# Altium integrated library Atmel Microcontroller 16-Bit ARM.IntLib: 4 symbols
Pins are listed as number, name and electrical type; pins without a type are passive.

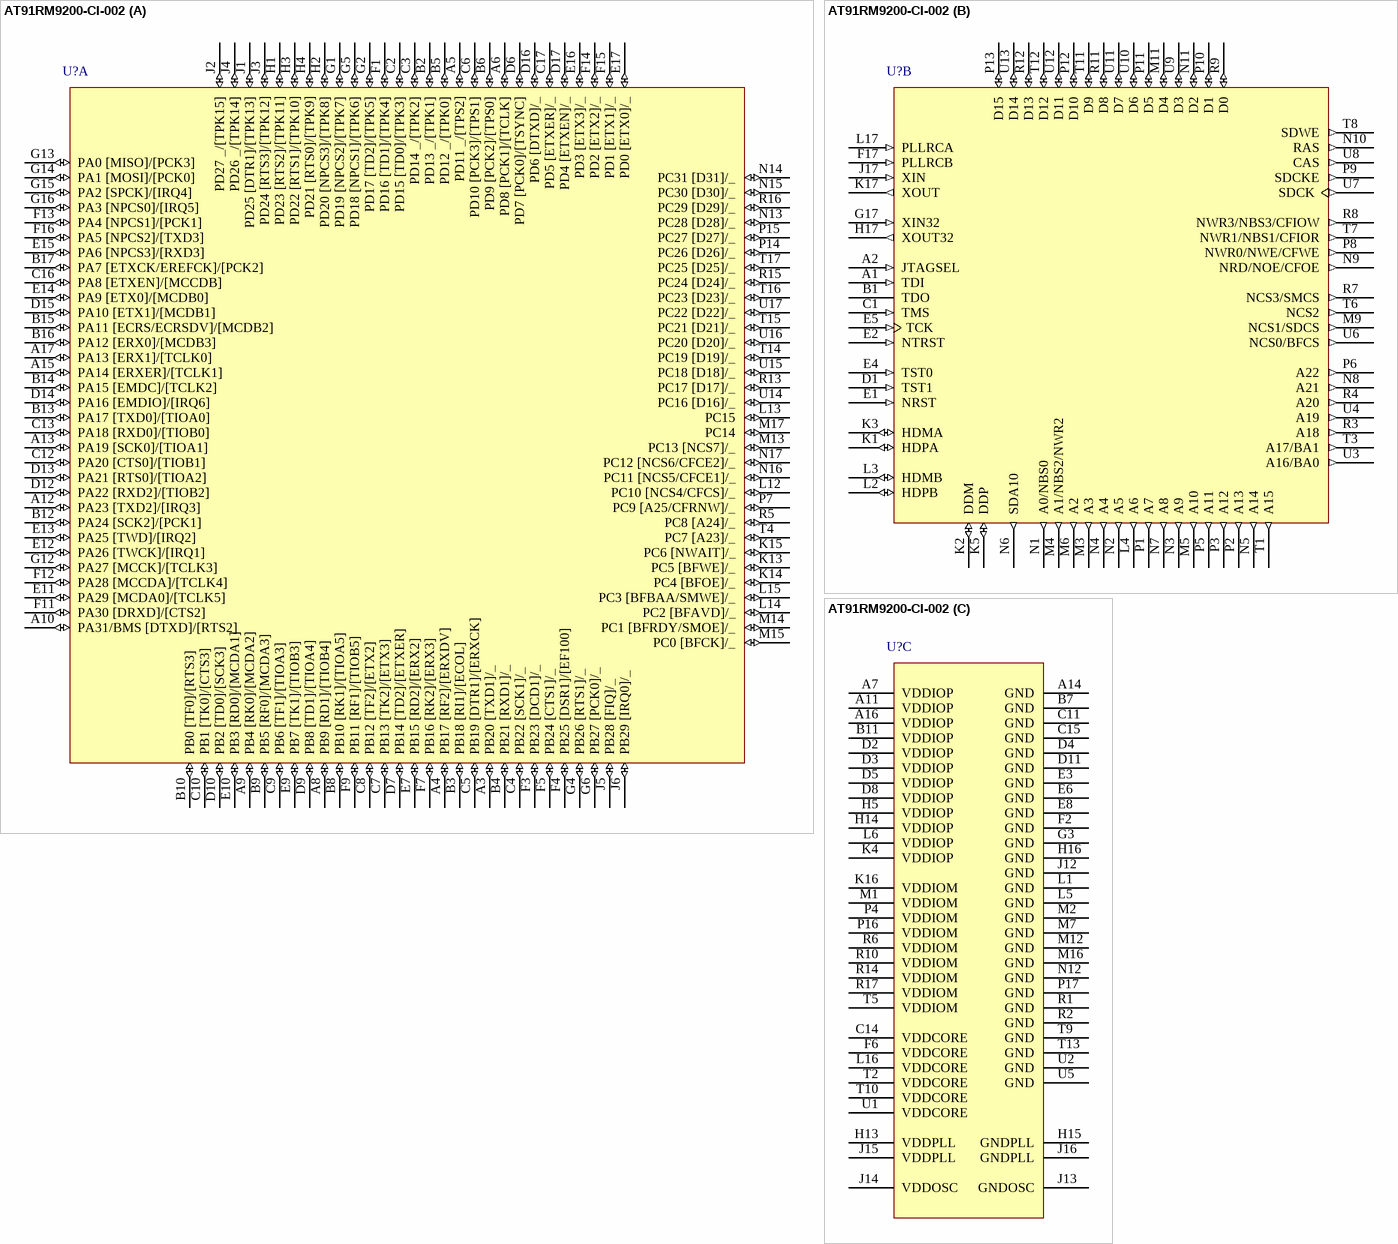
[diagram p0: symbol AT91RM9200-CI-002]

## AT91RM9200-CI-002
designator U?
16-Bit ARM Microcontroller, ARM9TDMI 32-bit RISC CPU, 16KB Instruction and 16KB Data caches, 256-Ball BGA, Industrial; Note: The Pin names in [ ] brackets indicate peripheral multiplexing function.
footprint BGA256 (BGA, 256-Leads, Body 15x15mm, Pitch 0.8mm)
3D model AT91RM9200-BGA256 (256-Ball Ball Grid Array 0.8 mm Pitch)
part A pins: A3 PB20 [TXD1]/_ (io), A4 PB17 [RF2]/[ERXDV] (io), A5 PD11 _/[TPS2] (io), A6 PD8 [PCK1]/[TCLK] (io), A8 PB9 [RD1]/[TIOB4] (io), A9 PB4 [RK0]/[MCDA2] (io), A10 PA31/BMS [DTXD]/[RTS2] (io), A12 PA23 [TXD2]/[IRQ3] (io), A13 PA19 [SCK0]/[TIOA1] (io), A15 PA14 [ERXER]/[TCLK1] (io), A17 PA13 [ERX1]/[TCLK0] (io), B2 PD13 _/[TPK1] (io), B3 PB18 [RI1]/[ECOL] (io), B4 PB21 [RXD1]/_ (io), B5 PD12 _/[TPK0] (io), B6 PD9 [PCK2]/[TPS0] (io), B8 PB10 [RK1]/[TIOA5] (io), B9 PB5 [RF0]/[MCDA3] (io), B10 PB0 [TF0]/[RTS3] (io), B12 PA24 [SCK2]/[PCK1] (io), B13 PA17 [TXD0]/[TIOA0] (io), B14 PA15 [EMDC]/[TCLK2] (io), B15 PA11 [ECRS/ECRSDV]/[MCDB2] (io), B16 PA12 [ERX0]/[MCDB3] (io), B17 PA7 [ETXCK/EREFCK]/[PCK2] (io), C2 PD15 [TD0]/[TPK3] (io), C3 PD14 _/[TPK2] (io), C4 PB22 [SCK1]/_ (io), C5 PB19 [DTR1]/[ERXCK] (io), C6 PD10 [PCK3]/[TPS1] (io), C7 PB13 [TK2]/[ETX3] (io), C8 PB12 [TF2]/[ETX2] (io), C9 PB6 [TF1]/[TIOA3] (io), C10 PB1 [TK0]/[CTS3] (io), C12 PA20 [CTS0]/[TIOB1] (io), C13 PA18 [RXD0]/[TIOB0] (io), C16 PA8 [ETXEN]/[MCCDB] (io), C17 PD5 [ETXER]/_ (io), D6 PD7 [PCK0]/[TSYNC] (io), D7 PB14 [TD2]/[ETXER] (io), D9 PB8 [TD1]/[TIOA4] (io), D10 PB2 [TD0]/[SCK3] (io), D12 PA22 [RXD2]/[TIOB2] (io), D13 PA21 [RTS0]/[TIOA2] (io), D14 PA16 [EMDIO]/[IRQ6] (io), D15 PA10 [ETX1]/[MCDB1] (io), D16 PD6 [DTXD]/_ (io), D17 PD4 [ETXEN]/_ (io), E7 PB15 [RD2]/[ERX2] (io), E9 PB7 [TK1]/[TIOB3] (io), E10 PB3 [RD0]/[MCDA1] (io), E11 PA29 [MCDA0]/[TCLK5] (io), E12 PA26 [TWCK]/[IRQ1] (io), E13 PA25 [TWD]/[IRQ2] (io), E14 PA9 [ETX0]/[MCDB0] (io), E15 PA6 [NPCS3]/[RXD3] (io), E16 PD3 [ETX3]/_ (io), E17 PD0 [ETX0]/_ (io), F1 PD16 [TD1]/[TPK4] (io), F3 PB23 [DCD1]/_ (io), F4 PB25 [DSR1]/[EF100] (io), F5 PB24 [CTS1]/_ (io), F7 PB16 [RK2]/[ERX3] (io), F9 PB11 [RF1]/[TIOB5] (io), F11 PA30 [DRXD]/[CTS2] (io), F12 PA28 [MCCDA]/[TCLK4] (io), F13 PA4 [NPCS1]/[PCK1] (io), F14 PD2 [ETX2]/_ (io), F15 PD1 [ETX1]/_ (io), F16 PA5 [NPCS2]/[TXD3] (io), G1 PD19 [NPCS2]/[TPK7] (io), G2 PD17 [TD2]/[TPK5] (io), G4 PB26 [RTS1]/_ (io), G5 PD18 [NPCS1]/[TPK6] (io), G6 PB27 [PCK0]/_ (io), G12 PA27 [MCCK]/[TCLK3] (io), G13 PA0 [MISO]/[PCK3] (io), G14 PA1 [MOSI]/[PCK0] (io), G15 PA2 [SPCK]/[IRQ4] (io), G16 PA3 [NPCS0]/[IRQ5] (io), H1 PD23 [RTS2]/[TPK11] (io), H2 PD20 [NPCS3]/[TPK8] (io), H3 PD22 [RTS1]/[TPK10] (io), H4 PD21 [RTS0]/[TPK9] (io), J1 PD25 [DTR1]/[TPK13] (io), J2 PD27 _/[TPK15] (io), J3 PD24 [RTS3]/[TPK12] (io), J4 PD26 _/[TPK14] (io), J5 PB28 [FIQ]/_ (io), J6 PB29 [IRQ0]/_ (io), K13 PC5 [BFWE]/_ (io), K14 PC4 [BFOE]/_ (io), K15 PC6 [NWAIT]/_ (io), L12 PC10 [NCS4/CFCS]/_ (io), L13 PC15 (io), L14 PC2 [BFAVD]/_ (io), L15 PC3 [BFBAA/SMWE]/_ (io), M13 PC13 [NCS7]/_ (io), M14 PC1 [BFRDY/SMOE]/_ (io), M15 PC0 [BFCK]/_ (io), M17 PC14 (io), N13 PC28 [D28]/_ (io), N14 PC31 [D31]/_ (io), N15 PC30 [D30]/_ (io), N16 PC11 [NCS5/CFCE1]/_ (io), N17 PC12 [NCS6/CFCE2]/_ (io), P7 PC9 [A25/CFRNW]/_ (io), P14 PC26 [D26]/_ (io), P15 PC27 [D27]/_ (io), R5 PC8 [A24]/_ (io), R13 PC17 [D17]/_ (io), R15 PC24 [D24]/_ (io), R16 PC29 [D29]/_ (io), T4 PC7 [A23]/_ (io), T14 PC19 [D19]/_ (io), T15 PC21 [D21]/_ (io), T16 PC23 [D23]/_ (io), T17 PC25 [D25]/_ (io), U14 PC16 [D16]/_ (io), U15 PC18 [D18]/_ (io), U16 PC20 [D20]/_ (io), U17 PC22 [D22]/_ (io)
part B pins: A1 TDI (in), A2 JTAGSEL (in), B1 TDO (hiz), C1 TMS (in), D1 TST1 (in), E1 NRST (in), E2 NTRST (in), E4 TST0 (in), E5 TCK (in), F17 PLLRCB (in), G17 XIN32 (in), H17 XOUT32 (out), J17 XIN (in), K1 HDPA (io), K2 DDM (io), K3 HDMA (io), K5 DDP (io), K17 XOUT (out), L2 HDPB (io), L3 HDMB (io), L4 A6 (out), L17 PLLRCA (in), M3 A3 (out), M4 A1/NBS2/NWR2 (out), M5 A10 (out), M6 A2 (out), M9 NCS1/SDCS (out), M11 D4 (io), N1 A0/NBS0 (out), N2 A5 (out), N3 A9 (out), N4 A4 (out), N5 A14 (out), N6 SDA10 (out), N7 A8 (out), N8 A21 (out), N9 NRD/NOE/CFOE (out), N10 RAS (out), N11 D2 (io), P1 A7 (out), P2 A13 (out), P3 A12 (out), P5 A11 (out), P6 A22 (out), P8 NWR0/NWE/CFWE (out), P9 SDCKE (out), P10 D1 (io), P11 D5 (io), P12 D10 (io), P13 D15 (io), R3 A18 (out), R4 A20 (out), R7 NCS3/SMCS (out), R8 NWR3/NBS3/CFIOW (out), R9 D0 (io), R11 D8 (io), R12 D13 (io), T1 A15 (out), T3 A17/BA1 (out), T6 NCS2 (out), T7 NWR1/NBS1/CFIOR (out), T8 SDWE (out), T11 D9 (io), T12 D12 (io), U3 A16/BA0 (out), U4 A19 (out), U6 NCS0/BFCS (out), U7 SDCK (out), U8 CAS (out), U9 D3 (io), U10 D6 (io), U11 D7 (io), U12 D11 (io), U13 D14 (io)
part C pins: A7 VDDIOP (power), A11 VDDIOP (power), A14 GND (power), A16 VDDIOP (power), B7 GND (power), B11 VDDIOP (power), C11 GND (power), C14 VDDCORE (power), C15 GND (power), D2 VDDIOP (power), D3 VDDIOP (power), D4 GND (power), D5 VDDIOP (power), D8 VDDIOP (power), D11 GND (power), E3 GND (power), E6 GND (power), E8 GND (power), F2 GND (power), F6 VDDCORE (power), G3 GND (power), H5 VDDIOP (power), H13 VDDPLL (power), H14 VDDIOP (power), H15 GNDPLL (power), H16 GND (power), J12 GND (power), J13 GNDOSC (power), J14 VDDOSC (power), J15 VDDPLL (power), J16 GNDPLL (power), K4 VDDIOP (power), K16 VDDIOM (power), L1 GND (power), L5 GND (power), L6 VDDIOP (power), L16 VDDCORE (power), M1 VDDIOM (power), M2 GND (power), M7 GND (power), M12 GND (power), M16 GND (power), N12 GND (power), P4 VDDIOM (power), P16 VDDIOM (power), P17 GND (power), R1 GND (power), R2 GND (power), R6 VDDIOM (power), R10 VDDIOM (power), R14 VDDIOM (power), R17 VDDIOM (power), T2 VDDCORE (power), T5 VDDIOM (power), T9 GND (power), T10 VDDCORE (power), T13 GND (power), U1 VDDCORE (power), U2 GND (power), U5 GND (power)

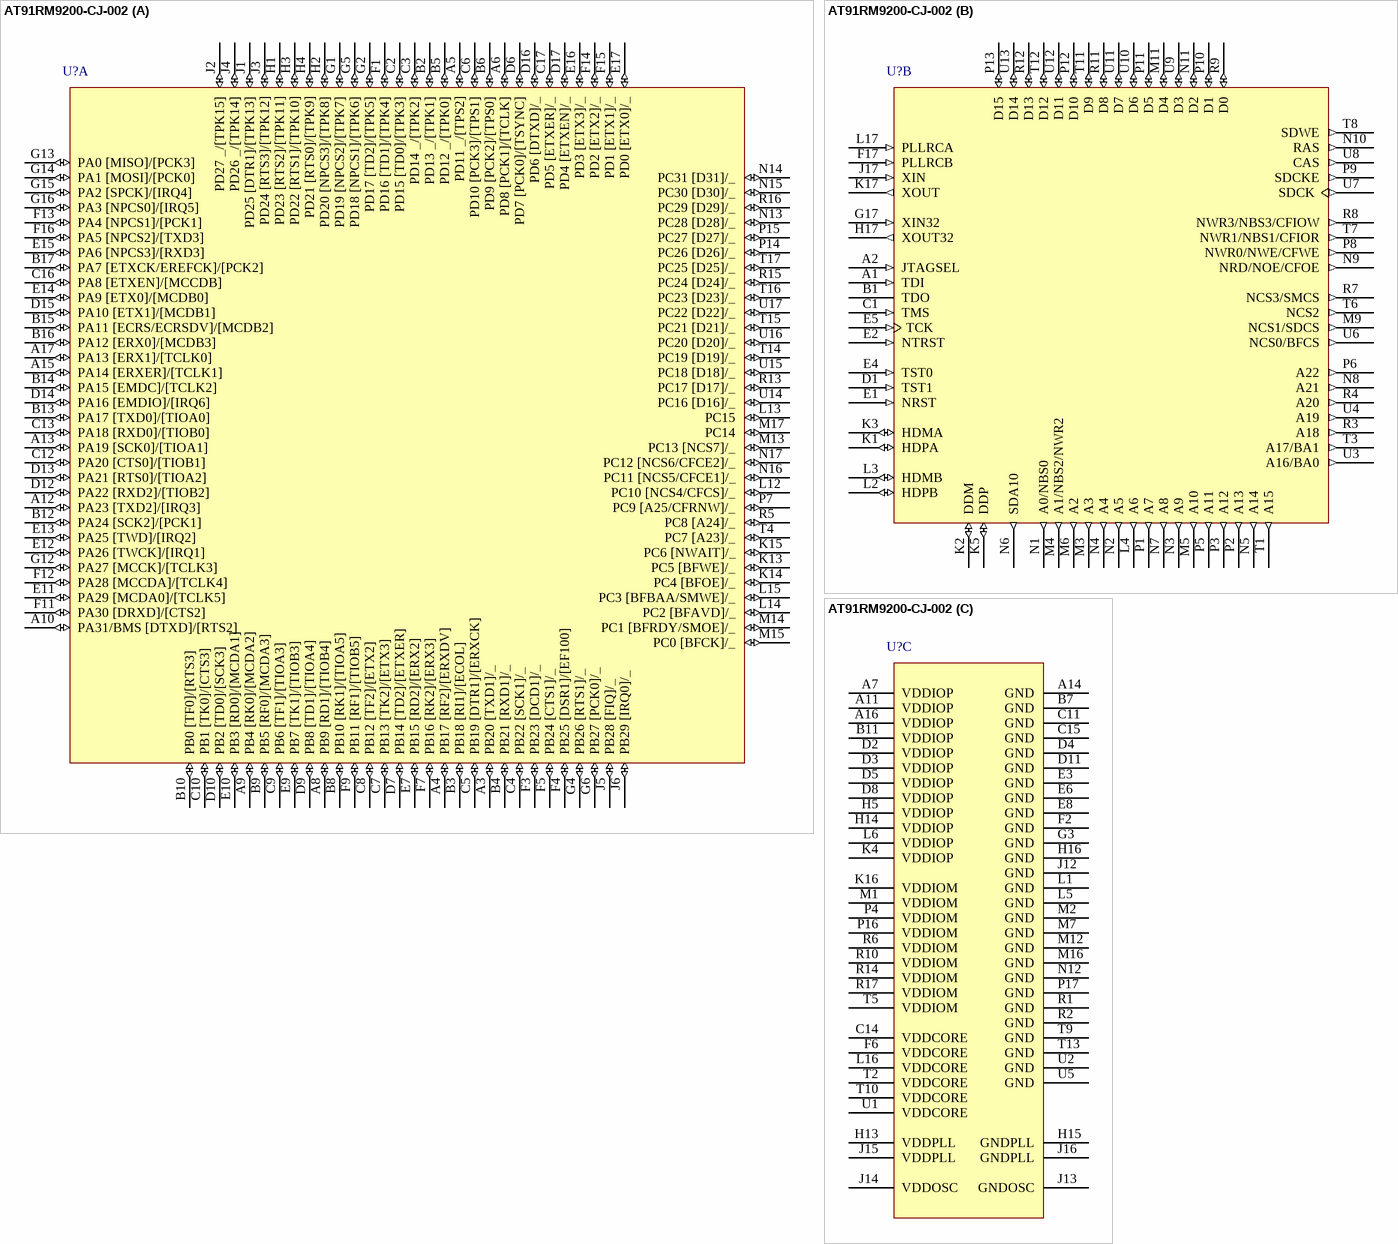
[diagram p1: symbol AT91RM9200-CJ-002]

## AT91RM9200-CJ-002
designator U?
16-Bit ARM Microcontroller, ARM9TDMI 32-bit RISC CPU, 16KB Instruction and 16KB Data caches, 256-Ball BGA, Industrial, Pb-free; Note: The Pin names in [ ] brackets indicate peripheral multiplexing function.
footprint BGA256 (BGA, 256-Leads, Body 15x15mm, Pitch 0.8mm)
3D model AT91RM9200-BGA256 (256-Ball Ball Grid Array 0.8 mm Pitch)
part A pins: A3 PB20 [TXD1]/_ (io), A4 PB17 [RF2]/[ERXDV] (io), A5 PD11 _/[TPS2] (io), A6 PD8 [PCK1]/[TCLK] (io), A8 PB9 [RD1]/[TIOB4] (io), A9 PB4 [RK0]/[MCDA2] (io), A10 PA31/BMS [DTXD]/[RTS2] (io), A12 PA23 [TXD2]/[IRQ3] (io), A13 PA19 [SCK0]/[TIOA1] (io), A15 PA14 [ERXER]/[TCLK1] (io), A17 PA13 [ERX1]/[TCLK0] (io), B2 PD13 _/[TPK1] (io), B3 PB18 [RI1]/[ECOL] (io), B4 PB21 [RXD1]/_ (io), B5 PD12 _/[TPK0] (io), B6 PD9 [PCK2]/[TPS0] (io), B8 PB10 [RK1]/[TIOA5] (io), B9 PB5 [RF0]/[MCDA3] (io), B10 PB0 [TF0]/[RTS3] (io), B12 PA24 [SCK2]/[PCK1] (io), B13 PA17 [TXD0]/[TIOA0] (io), B14 PA15 [EMDC]/[TCLK2] (io), B15 PA11 [ECRS/ECRSDV]/[MCDB2] (io), B16 PA12 [ERX0]/[MCDB3] (io), B17 PA7 [ETXCK/EREFCK]/[PCK2] (io), C2 PD15 [TD0]/[TPK3] (io), C3 PD14 _/[TPK2] (io), C4 PB22 [SCK1]/_ (io), C5 PB19 [DTR1]/[ERXCK] (io), C6 PD10 [PCK3]/[TPS1] (io), C7 PB13 [TK2]/[ETX3] (io), C8 PB12 [TF2]/[ETX2] (io), C9 PB6 [TF1]/[TIOA3] (io), C10 PB1 [TK0]/[CTS3] (io), C12 PA20 [CTS0]/[TIOB1] (io), C13 PA18 [RXD0]/[TIOB0] (io), C16 PA8 [ETXEN]/[MCCDB] (io), C17 PD5 [ETXER]/_ (io), D6 PD7 [PCK0]/[TSYNC] (io), D7 PB14 [TD2]/[ETXER] (io), D9 PB8 [TD1]/[TIOA4] (io), D10 PB2 [TD0]/[SCK3] (io), D12 PA22 [RXD2]/[TIOB2] (io), D13 PA21 [RTS0]/[TIOA2] (io), D14 PA16 [EMDIO]/[IRQ6] (io), D15 PA10 [ETX1]/[MCDB1] (io), D16 PD6 [DTXD]/_ (io), D17 PD4 [ETXEN]/_ (io), E7 PB15 [RD2]/[ERX2] (io), E9 PB7 [TK1]/[TIOB3] (io), E10 PB3 [RD0]/[MCDA1] (io), E11 PA29 [MCDA0]/[TCLK5] (io), E12 PA26 [TWCK]/[IRQ1] (io), E13 PA25 [TWD]/[IRQ2] (io), E14 PA9 [ETX0]/[MCDB0] (io), E15 PA6 [NPCS3]/[RXD3] (io), E16 PD3 [ETX3]/_ (io), E17 PD0 [ETX0]/_ (io), F1 PD16 [TD1]/[TPK4] (io), F3 PB23 [DCD1]/_ (io), F4 PB25 [DSR1]/[EF100] (io), F5 PB24 [CTS1]/_ (io), F7 PB16 [RK2]/[ERX3] (io), F9 PB11 [RF1]/[TIOB5] (io), F11 PA30 [DRXD]/[CTS2] (io), F12 PA28 [MCCDA]/[TCLK4] (io), F13 PA4 [NPCS1]/[PCK1] (io), F14 PD2 [ETX2]/_ (io), F15 PD1 [ETX1]/_ (io), F16 PA5 [NPCS2]/[TXD3] (io), G1 PD19 [NPCS2]/[TPK7] (io), G2 PD17 [TD2]/[TPK5] (io), G4 PB26 [RTS1]/_ (io), G5 PD18 [NPCS1]/[TPK6] (io), G6 PB27 [PCK0]/_ (io), G12 PA27 [MCCK]/[TCLK3] (io), G13 PA0 [MISO]/[PCK3] (io), G14 PA1 [MOSI]/[PCK0] (io), G15 PA2 [SPCK]/[IRQ4] (io), G16 PA3 [NPCS0]/[IRQ5] (io), H1 PD23 [RTS2]/[TPK11] (io), H2 PD20 [NPCS3]/[TPK8] (io), H3 PD22 [RTS1]/[TPK10] (io), H4 PD21 [RTS0]/[TPK9] (io), J1 PD25 [DTR1]/[TPK13] (io), J2 PD27 _/[TPK15] (io), J3 PD24 [RTS3]/[TPK12] (io), J4 PD26 _/[TPK14] (io), J5 PB28 [FIQ]/_ (io), J6 PB29 [IRQ0]/_ (io), K13 PC5 [BFWE]/_ (io), K14 PC4 [BFOE]/_ (io), K15 PC6 [NWAIT]/_ (io), L12 PC10 [NCS4/CFCS]/_ (io), L13 PC15 (io), L14 PC2 [BFAVD]/_ (io), L15 PC3 [BFBAA/SMWE]/_ (io), M13 PC13 [NCS7]/_ (io), M14 PC1 [BFRDY/SMOE]/_ (io), M15 PC0 [BFCK]/_ (io), M17 PC14 (io), N13 PC28 [D28]/_ (io), N14 PC31 [D31]/_ (io), N15 PC30 [D30]/_ (io), N16 PC11 [NCS5/CFCE1]/_ (io), N17 PC12 [NCS6/CFCE2]/_ (io), P7 PC9 [A25/CFRNW]/_ (io), P14 PC26 [D26]/_ (io), P15 PC27 [D27]/_ (io), R5 PC8 [A24]/_ (io), R13 PC17 [D17]/_ (io), R15 PC24 [D24]/_ (io), R16 PC29 [D29]/_ (io), T4 PC7 [A23]/_ (io), T14 PC19 [D19]/_ (io), T15 PC21 [D21]/_ (io), T16 PC23 [D23]/_ (io), T17 PC25 [D25]/_ (io), U14 PC16 [D16]/_ (io), U15 PC18 [D18]/_ (io), U16 PC20 [D20]/_ (io), U17 PC22 [D22]/_ (io)
part B pins: A1 TDI (in), A2 JTAGSEL (in), B1 TDO (hiz), C1 TMS (in), D1 TST1 (in), E1 NRST (in), E2 NTRST (in), E4 TST0 (in), E5 TCK (in), F17 PLLRCB (in), G17 XIN32 (in), H17 XOUT32 (out), J17 XIN (in), K1 HDPA (io), K2 DDM (io), K3 HDMA (io), K5 DDP (io), K17 XOUT (out), L2 HDPB (io), L3 HDMB (io), L4 A6 (out), L17 PLLRCA (in), M3 A3 (out), M4 A1/NBS2/NWR2 (out), M5 A10 (out), M6 A2 (out), M9 NCS1/SDCS (out), M11 D4 (io), N1 A0/NBS0 (out), N2 A5 (out), N3 A9 (out), N4 A4 (out), N5 A14 (out), N6 SDA10 (out), N7 A8 (out), N8 A21 (out), N9 NRD/NOE/CFOE (out), N10 RAS (out), N11 D2 (io), P1 A7 (out), P2 A13 (out), P3 A12 (out), P5 A11 (out), P6 A22 (out), P8 NWR0/NWE/CFWE (out), P9 SDCKE (out), P10 D1 (io), P11 D5 (io), P12 D10 (io), P13 D15 (io), R3 A18 (out), R4 A20 (out), R7 NCS3/SMCS (out), R8 NWR3/NBS3/CFIOW (out), R9 D0 (io), R11 D8 (io), R12 D13 (io), T1 A15 (out), T3 A17/BA1 (out), T6 NCS2 (out), T7 NWR1/NBS1/CFIOR (out), T8 SDWE (out), T11 D9 (io), T12 D12 (io), U3 A16/BA0 (out), U4 A19 (out), U6 NCS0/BFCS (out), U7 SDCK (out), U8 CAS (out), U9 D3 (io), U10 D6 (io), U11 D7 (io), U12 D11 (io), U13 D14 (io)
part C pins: A7 VDDIOP (power), A11 VDDIOP (power), A14 GND (power), A16 VDDIOP (power), B7 GND (power), B11 VDDIOP (power), C11 GND (power), C14 VDDCORE (power), C15 GND (power), D2 VDDIOP (power), D3 VDDIOP (power), D4 GND (power), D5 VDDIOP (power), D8 VDDIOP (power), D11 GND (power), E3 GND (power), E6 GND (power), E8 GND (power), F2 GND (power), F6 VDDCORE (power), G3 GND (power), H5 VDDIOP (power), H13 VDDPLL (power), H14 VDDIOP (power), H15 GNDPLL (power), H16 GND (power), J12 GND (power), J13 GNDOSC (power), J14 VDDOSC (power), J15 VDDPLL (power), J16 GNDPLL (power), K4 VDDIOP (power), K16 VDDIOM (power), L1 GND (power), L5 GND (power), L6 VDDIOP (power), L16 VDDCORE (power), M1 VDDIOM (power), M2 GND (power), M7 GND (power), M12 GND (power), M16 GND (power), N12 GND (power), P4 VDDIOM (power), P16 VDDIOM (power), P17 GND (power), R1 GND (power), R2 GND (power), R6 VDDIOM (power), R10 VDDIOM (power), R14 VDDIOM (power), R17 VDDIOM (power), T2 VDDCORE (power), T5 VDDIOM (power), T9 GND (power), T10 VDDCORE (power), T13 GND (power), U1 VDDCORE (power), U2 GND (power), U5 GND (power)

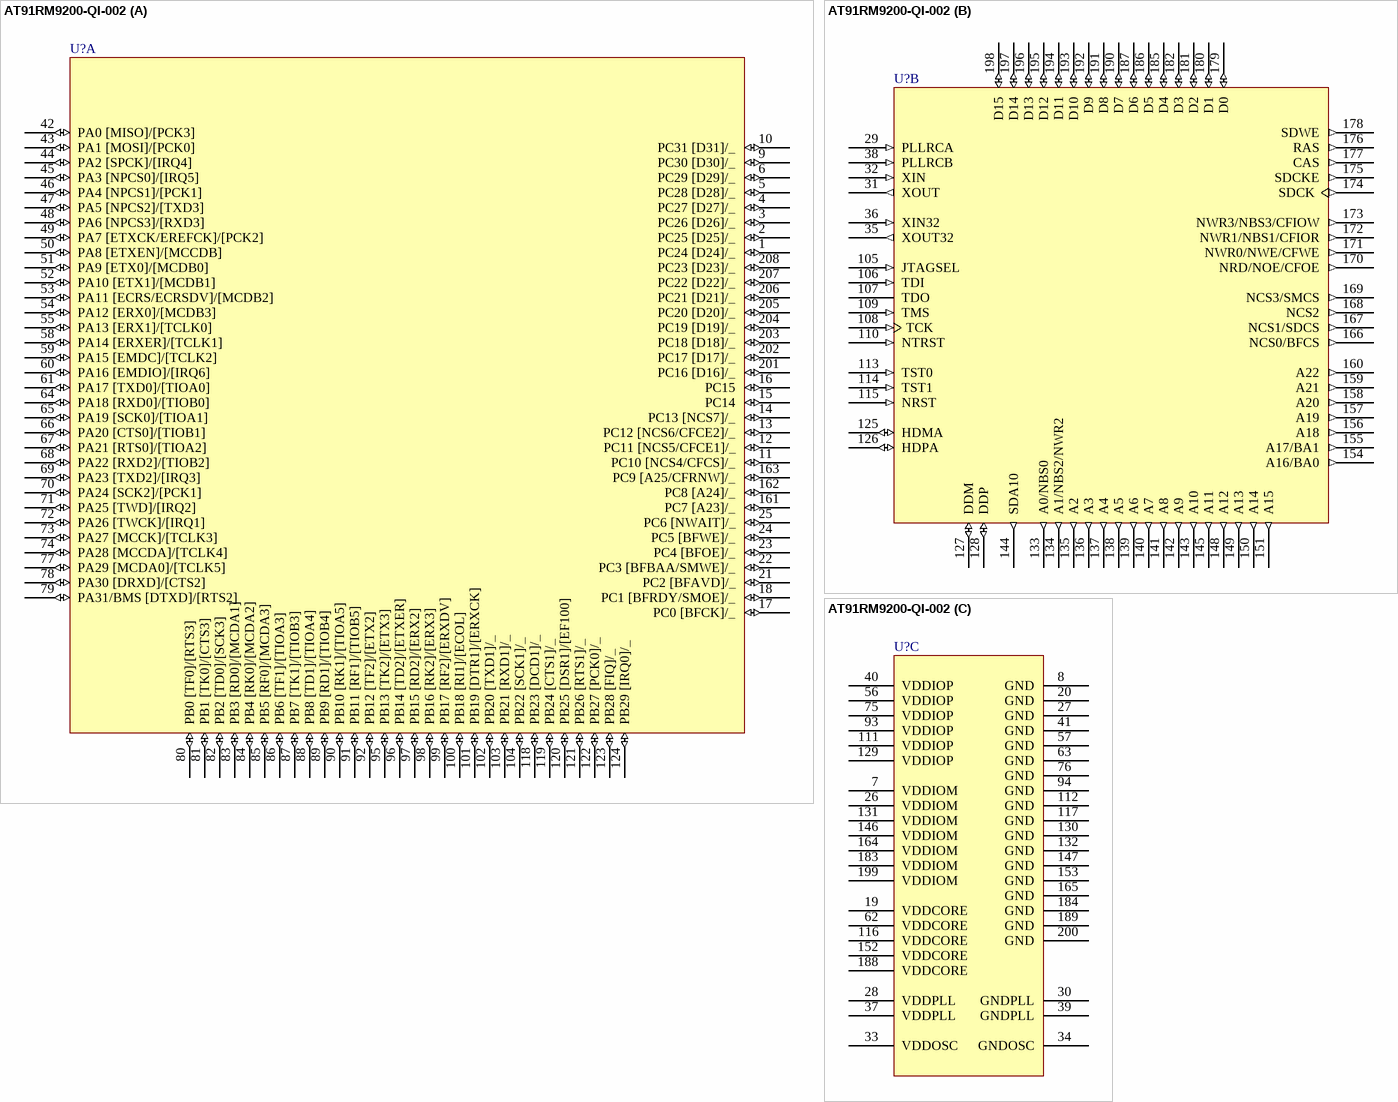
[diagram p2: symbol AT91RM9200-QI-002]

## AT91RM9200-QI-002
designator U?
16-Bit ARM Microcontroller, ARM9TDMI 32-bit RISC CPU, 16KB Instruction and 16KB Data caches, 208-Pin PQFP, Industrial; Note: The Pin names in [ ] brackets indicate peripheral multiplexing function.
footprint QFP208_N (Shrink QFP, 208-Leads, Body 28x28mm, Pitch 0.5mm, IPC Medium Density)
footprint QFP208_L (Shrink QFP, 208-Leads, Body 28x28mm, Pitch 0.5mm, IPC High Density)
footprint QFP208_M (Shrink QFP, 208-Leads, Body 28x28mm, Pitch 0.5mm, IPC Low Density)
3D model AT91RM9200-QFP208 (208-Pin Plastic Shrink Quad Flat Pack 0.5 mm Pitch)
part A pins: 1 PC24 [D24]/_ (io), 2 PC25 [D25]/_ (io), 3 PC26 [D26]/_ (io), 4 PC27 [D27]/_ (io), 5 PC28 [D28]/_ (io), 6 PC29 [D29]/_ (io), 9 PC30 [D30]/_ (io), 10 PC31 [D31]/_ (io), 11 PC10 [NCS4/CFCS]/_ (io), 12 PC11 [NCS5/CFCE1]/_ (io), 13 PC12 [NCS6/CFCE2]/_ (io), 14 PC13 [NCS7]/_ (io), 15 PC14 (io), 16 PC15 (io), 17 PC0 [BFCK]/_ (io), 18 PC1 [BFRDY/SMOE]/_ (io), 21 PC2 [BFAVD]/_ (io), 22 PC3 [BFBAA/SMWE]/_ (io), 23 PC4 [BFOE]/_ (io), 24 PC5 [BFWE]/_ (io), 25 PC6 [NWAIT]/_ (io), 42 PA0 [MISO]/[PCK3] (io), 43 PA1 [MOSI]/[PCK0] (io), 44 PA2 [SPCK]/[IRQ4] (io), 45 PA3 [NPCS0]/[IRQ5] (io), 46 PA4 [NPCS1]/[PCK1] (io), 47 PA5 [NPCS2]/[TXD3] (io), 48 PA6 [NPCS3]/[RXD3] (io), 49 PA7 [ETXCK/EREFCK]/[PCK2] (io), 50 PA8 [ETXEN]/[MCCDB] (io), 51 PA9 [ETX0]/[MCDB0] (io), 52 PA10 [ETX1]/[MCDB1] (io), 53 PA11 [ECRS/ECRSDV]/[MCDB2] (io), 54 PA12 [ERX0]/[MCDB3] (io), 55 PA13 [ERX1]/[TCLK0] (io), 58 PA14 [ERXER]/[TCLK1] (io), 59 PA15 [EMDC]/[TCLK2] (io), 60 PA16 [EMDIO]/[IRQ6] (io), 61 PA17 [TXD0]/[TIOA0] (io), 64 PA18 [RXD0]/[TIOB0] (io), 65 PA19 [SCK0]/[TIOA1] (io), 66 PA20 [CTS0]/[TIOB1] (io), 67 PA21 [RTS0]/[TIOA2] (io), 68 PA22 [RXD2]/[TIOB2] (io), 69 PA23 [TXD2]/[IRQ3] (io), 70 PA24 [SCK2]/[PCK1] (io), 71 PA25 [TWD]/[IRQ2] (io), 72 PA26 [TWCK]/[IRQ1] (io), 73 PA27 [MCCK]/[TCLK3] (io), 74 PA28 [MCCDA]/[TCLK4] (io), 77 PA29 [MCDA0]/[TCLK5] (io), 78 PA30 [DRXD]/[CTS2] (io), 79 PA31/BMS [DTXD]/[RTS2] (io), 80 PB0 [TF0]/[RTS3] (io), 81 PB1 [TK0]/[CTS3] (io), 82 PB2 [TD0]/[SCK3] (io), 83 PB3 [RD0]/[MCDA1] (io), 84 PB4 [RK0]/[MCDA2] (io), 85 PB5 [RF0]/[MCDA3] (io), 86 PB6 [TF1]/[TIOA3] (io), 87 PB7 [TK1]/[TIOB3] (io), 88 PB8 [TD1]/[TIOA4] (io), 89 PB9 [RD1]/[TIOB4] (io), 90 PB10 [RK1]/[TIOA5] (io), 91 PB11 [RF1]/[TIOB5] (io), 92 PB12 [TF2]/[ETX2] (io), 95 PB13 [TK2]/[ETX3] (io), 96 PB14 [TD2]/[ETXER] (io), 97 PB15 [RD2]/[ERX2] (io), 98 PB16 [RK2]/[ERX3] (io), 99 PB17 [RF2]/[ERXDV] (io), 100 PB18 [RI1]/[ECOL] (io), 101 PB19 [DTR1]/[ERXCK] (io), 102 PB20 [TXD1]/_ (io), 103 PB21 [RXD1]/_ (io), 104 PB22 [SCK1]/_ (io), 118 PB23 [DCD1]/_ (io), 119 PB24 [CTS1]/_ (io), 120 PB25 [DSR1]/[EF100] (io), 121 PB26 [RTS1]/_ (io), 122 PB27 [PCK0]/_ (io), 123 PB28 [FIQ]/_ (io), 124 PB29 [IRQ0]/_ (io), 161 PC7 [A23]/_ (io), 162 PC8 [A24]/_ (io), 163 PC9 [A25/CFRNW]/_ (io), 201 PC16 [D16]/_ (io), 202 PC17 [D17]/_ (io), 203 PC18 [D18]/_ (io), 204 PC19 [D19]/_ (io), 205 PC20 [D20]/_ (io), 206 PC21 [D21]/_ (io), 207 PC22 [D22]/_ (io), 208 PC23 [D23]/_ (io)
part B pins: 29 PLLRCA (in), 31 XOUT (out), 32 XIN (in), 35 XOUT32 (out), 36 XIN32 (in), 38 PLLRCB (in), 105 JTAGSEL (in), 106 TDI (in), 107 TDO (hiz), 108 TCK (in), 109 TMS (in), 110 NTRST (in), 113 TST0 (in), 114 TST1 (in), 115 NRST (in), 125 HDMA (io), 126 HDPA (io), 127 DDM (io), 128 DDP (io), 133 A0/NBS0 (out), 134 A1/NBS2/NWR2 (out), 135 A2 (out), 136 A3 (out), 137 A4 (out), 138 A5 (out), 139 A6 (out), 140 A7 (out), 141 A8 (out), 142 A9 (out), 143 A10 (out), 144 SDA10 (out), 145 A11 (out), 148 A12 (out), 149 A13 (out), 150 A14 (out), 151 A15 (out), 154 A16/BA0 (out), 155 A17/BA1 (out), 156 A18 (out), 157 A19 (out), 158 A20 (out), 159 A21 (out), 160 A22 (out), 166 NCS0/BFCS (out), 167 NCS1/SDCS (out), 168 NCS2 (out), 169 NCS3/SMCS (out), 170 NRD/NOE/CFOE (out), 171 NWR0/NWE/CFWE (out), 172 NWR1/NBS1/CFIOR (out), 173 NWR3/NBS3/CFIOW (out), 174 SDCK (out), 175 SDCKE (out), 176 RAS (out), 177 CAS (out), 178 SDWE (out), 179 D0 (io), 180 D1 (io), 181 D2 (io), 182 D3 (io), 185 D4 (io), 186 D5 (io), 187 D6 (io), 190 D7 (io), 191 D8 (io), 192 D9 (io), 193 D10 (io), 194 D11 (io), 195 D12 (io), 196 D13 (io), 197 D14 (io), 198 D15 (io)
part C pins: 7 VDDIOM (power), 8 GND (power), 19 VDDCORE (power), 20 GND (power), 26 VDDIOM (power), 27 GND (power), 28 VDDPLL (power), 30 GNDPLL (power), 33 VDDOSC (power), 34 GNDOSC (power), 37 VDDPLL (power), 39 GNDPLL (power), 40 VDDIOP (power), 41 GND (power), 56 VDDIOP (power), 57 GND (power), 62 VDDCORE (power), 63 GND (power), 75 VDDIOP (power), 76 GND (power), 93 VDDIOP (power), 94 GND (power), 111 VDDIOP (power), 112 GND (power), 116 VDDCORE (power), 117 GND (power), 129 VDDIOP (power), 130 GND (power), 131 VDDIOM (power), 132 GND (power), 146 VDDIOM (power), 147 GND (power), 152 VDDCORE (power), 153 GND (power), 164 VDDIOM (power), 165 GND (power), 183 VDDIOM (power), 184 GND (power), 188 VDDCORE (power), 189 GND (power), 199 VDDIOM (power), 200 GND (power)

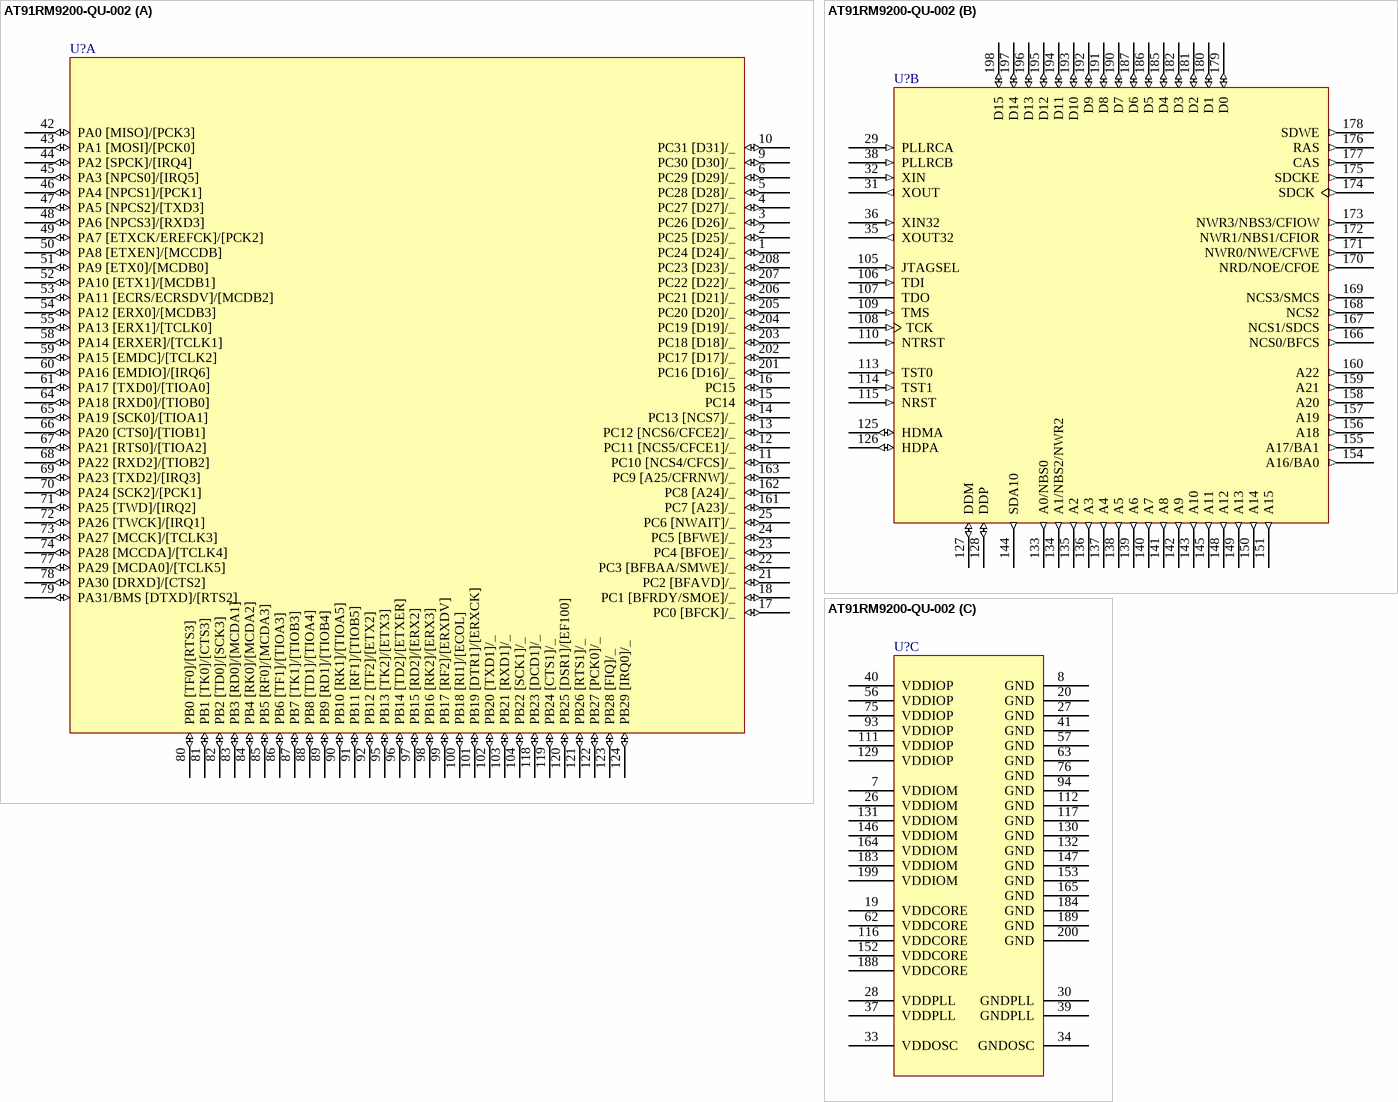
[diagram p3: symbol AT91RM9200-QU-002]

## AT91RM9200-QU-002
designator U?
16-Bit ARM Microcontroller, ARM9TDMI 32-bit RISC CPU, 16KB Instruction and 16KB Data caches, 208-Pin PQFP, Industrial, Pb-free; Note: The Pin names in [ ] brackets indicate peripheral multiplexing function.
footprint QFP208_N (Shrink QFP, 208-Leads, Body 28x28mm, Pitch 0.5mm, IPC Medium Density)
footprint QFP208_L (Shrink QFP, 208-Leads, Body 28x28mm, Pitch 0.5mm, IPC High Density)
footprint QFP208_M (Shrink QFP, 208-Leads, Body 28x28mm, Pitch 0.5mm, IPC Low Density)
3D model AT91RM9200-QFP208 (208-Pin Plastic Shrink Quad Flat Pack 0.5 mm Pitch)
part A pins: 1 PC24 [D24]/_ (io), 2 PC25 [D25]/_ (io), 3 PC26 [D26]/_ (io), 4 PC27 [D27]/_ (io), 5 PC28 [D28]/_ (io), 6 PC29 [D29]/_ (io), 9 PC30 [D30]/_ (io), 10 PC31 [D31]/_ (io), 11 PC10 [NCS4/CFCS]/_ (io), 12 PC11 [NCS5/CFCE1]/_ (io), 13 PC12 [NCS6/CFCE2]/_ (io), 14 PC13 [NCS7]/_ (io), 15 PC14 (io), 16 PC15 (io), 17 PC0 [BFCK]/_ (io), 18 PC1 [BFRDY/SMOE]/_ (io), 21 PC2 [BFAVD]/_ (io), 22 PC3 [BFBAA/SMWE]/_ (io), 23 PC4 [BFOE]/_ (io), 24 PC5 [BFWE]/_ (io), 25 PC6 [NWAIT]/_ (io), 42 PA0 [MISO]/[PCK3] (io), 43 PA1 [MOSI]/[PCK0] (io), 44 PA2 [SPCK]/[IRQ4] (io), 45 PA3 [NPCS0]/[IRQ5] (io), 46 PA4 [NPCS1]/[PCK1] (io), 47 PA5 [NPCS2]/[TXD3] (io), 48 PA6 [NPCS3]/[RXD3] (io), 49 PA7 [ETXCK/EREFCK]/[PCK2] (io), 50 PA8 [ETXEN]/[MCCDB] (io), 51 PA9 [ETX0]/[MCDB0] (io), 52 PA10 [ETX1]/[MCDB1] (io), 53 PA11 [ECRS/ECRSDV]/[MCDB2] (io), 54 PA12 [ERX0]/[MCDB3] (io), 55 PA13 [ERX1]/[TCLK0] (io), 58 PA14 [ERXER]/[TCLK1] (io), 59 PA15 [EMDC]/[TCLK2] (io), 60 PA16 [EMDIO]/[IRQ6] (io), 61 PA17 [TXD0]/[TIOA0] (io), 64 PA18 [RXD0]/[TIOB0] (io), 65 PA19 [SCK0]/[TIOA1] (io), 66 PA20 [CTS0]/[TIOB1] (io), 67 PA21 [RTS0]/[TIOA2] (io), 68 PA22 [RXD2]/[TIOB2] (io), 69 PA23 [TXD2]/[IRQ3] (io), 70 PA24 [SCK2]/[PCK1] (io), 71 PA25 [TWD]/[IRQ2] (io), 72 PA26 [TWCK]/[IRQ1] (io), 73 PA27 [MCCK]/[TCLK3] (io), 74 PA28 [MCCDA]/[TCLK4] (io), 77 PA29 [MCDA0]/[TCLK5] (io), 78 PA30 [DRXD]/[CTS2] (io), 79 PA31/BMS [DTXD]/[RTS2] (io), 80 PB0 [TF0]/[RTS3] (io), 81 PB1 [TK0]/[CTS3] (io), 82 PB2 [TD0]/[SCK3] (io), 83 PB3 [RD0]/[MCDA1] (io), 84 PB4 [RK0]/[MCDA2] (io), 85 PB5 [RF0]/[MCDA3] (io), 86 PB6 [TF1]/[TIOA3] (io), 87 PB7 [TK1]/[TIOB3] (io), 88 PB8 [TD1]/[TIOA4] (io), 89 PB9 [RD1]/[TIOB4] (io), 90 PB10 [RK1]/[TIOA5] (io), 91 PB11 [RF1]/[TIOB5] (io), 92 PB12 [TF2]/[ETX2] (io), 95 PB13 [TK2]/[ETX3] (io), 96 PB14 [TD2]/[ETXER] (io), 97 PB15 [RD2]/[ERX2] (io), 98 PB16 [RK2]/[ERX3] (io), 99 PB17 [RF2]/[ERXDV] (io), 100 PB18 [RI1]/[ECOL] (io), 101 PB19 [DTR1]/[ERXCK] (io), 102 PB20 [TXD1]/_ (io), 103 PB21 [RXD1]/_ (io), 104 PB22 [SCK1]/_ (io), 118 PB23 [DCD1]/_ (io), 119 PB24 [CTS1]/_ (io), 120 PB25 [DSR1]/[EF100] (io), 121 PB26 [RTS1]/_ (io), 122 PB27 [PCK0]/_ (io), 123 PB28 [FIQ]/_ (io), 124 PB29 [IRQ0]/_ (io), 161 PC7 [A23]/_ (io), 162 PC8 [A24]/_ (io), 163 PC9 [A25/CFRNW]/_ (io), 201 PC16 [D16]/_ (io), 202 PC17 [D17]/_ (io), 203 PC18 [D18]/_ (io), 204 PC19 [D19]/_ (io), 205 PC20 [D20]/_ (io), 206 PC21 [D21]/_ (io), 207 PC22 [D22]/_ (io), 208 PC23 [D23]/_ (io)
part B pins: 29 PLLRCA (in), 31 XOUT (out), 32 XIN (in), 35 XOUT32 (out), 36 XIN32 (in), 38 PLLRCB (in), 105 JTAGSEL (in), 106 TDI (in), 107 TDO (hiz), 108 TCK (in), 109 TMS (in), 110 NTRST (in), 113 TST0 (in), 114 TST1 (in), 115 NRST (in), 125 HDMA (io), 126 HDPA (io), 127 DDM (io), 128 DDP (io), 133 A0/NBS0 (out), 134 A1/NBS2/NWR2 (out), 135 A2 (out), 136 A3 (out), 137 A4 (out), 138 A5 (out), 139 A6 (out), 140 A7 (out), 141 A8 (out), 142 A9 (out), 143 A10 (out), 144 SDA10 (out), 145 A11 (out), 148 A12 (out), 149 A13 (out), 150 A14 (out), 151 A15 (out), 154 A16/BA0 (out), 155 A17/BA1 (out), 156 A18 (out), 157 A19 (out), 158 A20 (out), 159 A21 (out), 160 A22 (out), 166 NCS0/BFCS (out), 167 NCS1/SDCS (out), 168 NCS2 (out), 169 NCS3/SMCS (out), 170 NRD/NOE/CFOE (out), 171 NWR0/NWE/CFWE (out), 172 NWR1/NBS1/CFIOR (out), 173 NWR3/NBS3/CFIOW (out), 174 SDCK (out), 175 SDCKE (out), 176 RAS (out), 177 CAS (out), 178 SDWE (out), 179 D0 (io), 180 D1 (io), 181 D2 (io), 182 D3 (io), 185 D4 (io), 186 D5 (io), 187 D6 (io), 190 D7 (io), 191 D8 (io), 192 D9 (io), 193 D10 (io), 194 D11 (io), 195 D12 (io), 196 D13 (io), 197 D14 (io), 198 D15 (io)
part C pins: 7 VDDIOM (power), 8 GND (power), 19 VDDCORE (power), 20 GND (power), 26 VDDIOM (power), 27 GND (power), 28 VDDPLL (power), 30 GNDPLL (power), 33 VDDOSC (power), 34 GNDOSC (power), 37 VDDPLL (power), 39 GNDPLL (power), 40 VDDIOP (power), 41 GND (power), 56 VDDIOP (power), 57 GND (power), 62 VDDCORE (power), 63 GND (power), 75 VDDIOP (power), 76 GND (power), 93 VDDIOP (power), 94 GND (power), 111 VDDIOP (power), 112 GND (power), 116 VDDCORE (power), 117 GND (power), 129 VDDIOP (power), 130 GND (power), 131 VDDIOM (power), 132 GND (power), 146 VDDIOM (power), 147 GND (power), 152 VDDCORE (power), 153 GND (power), 164 VDDIOM (power), 165 GND (power), 183 VDDIOM (power), 184 GND (power), 188 VDDCORE (power), 189 GND (power), 199 VDDIOM (power), 200 GND (power)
